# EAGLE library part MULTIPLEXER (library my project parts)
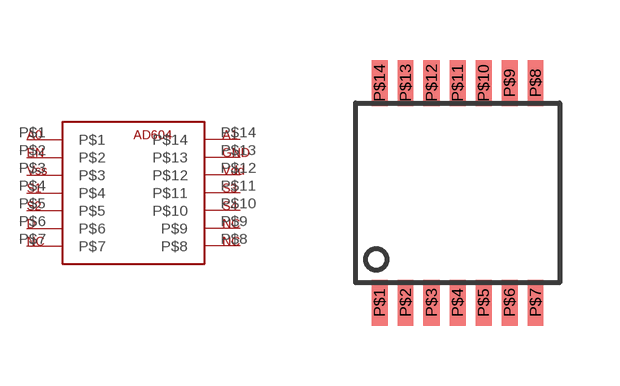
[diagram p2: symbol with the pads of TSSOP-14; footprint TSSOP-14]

Designator prefix -

## MULTIPLEXER  [TSSOP-14]
P$1  P$1
P$2  P$2
P$3  P$3
P$4  P$4
P$5  P$5
P$6  P$6
P$7  P$7
P$8  P$8
P$9  P$9
P$10  P$10
P$11  P$11
P$12  P$12
P$13  P$13
P$14  P$14

## Footprint TSSOP-14 (pad centres in mm)
smd 0.4 x 1.15: P$1 -1.95,-2.75; P$2 -1.3,-2.75; P$3 -0.65,-2.75; P$4 0,-2.75; P$5 0.65,-2.75; P$6 1.3,-2.75; P$7 1.95,-2.75; P$8 1.95,2.75; P$9 1.3,2.75; P$10 0.65,2.75; P$11 0,2.75; P$12 -0.65,2.75; P$13 -1.3,2.75; P$14 -1.95,2.75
